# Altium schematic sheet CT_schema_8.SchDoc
size 252 x 159 mm
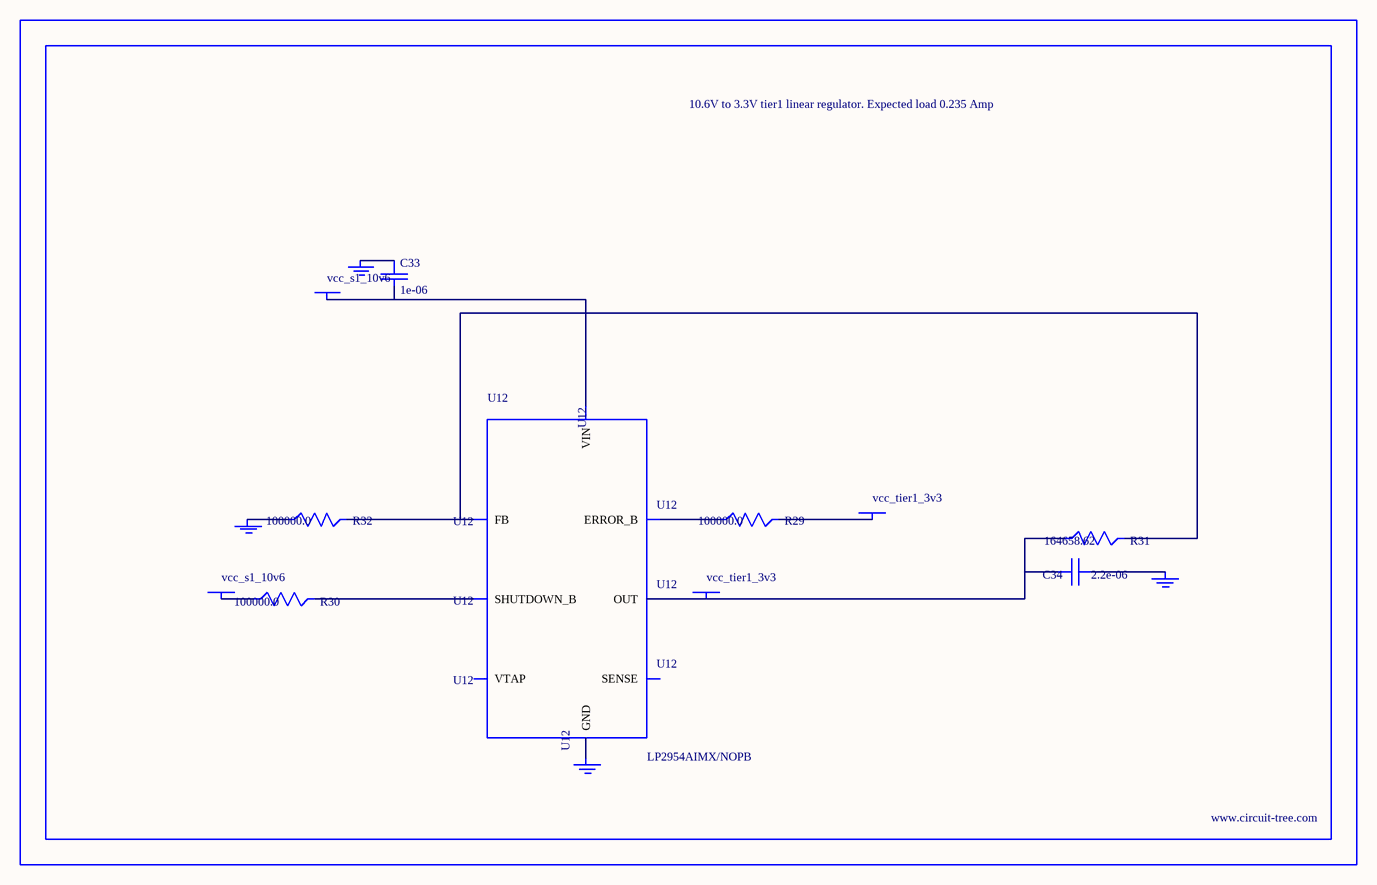
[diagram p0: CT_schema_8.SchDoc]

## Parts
BORDER7  (no value)
C33  1e-06  [EXV-9B]
C34  2.2e-06  [EXV-9B]
GND_INSTANCE_7_0  (no value)
GND_INSTANCE_7_1  (no value)
GND_INSTANCE_7_2  (no value)
GND_INSTANCE_7_3  (no value)
POWER_INSTANCE_7_0  vcc_s1_10v6
POWER_INSTANCE_7_1  vcc_tier1_3v3
POWER_INSTANCE_7_2  vcc_s1_10v6
POWER_INSTANCE_7_3  vcc_tier1_3v3
R29  100000.0  [R0603]
R30  100000.0  [R0603]
R31  164658.62  [R0603]
R32  100000.0  [R0603]
U12  LP2954AIMX/NOPB  [LP2954]

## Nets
NetC33_1: C33.1 GND_INSTANCE_7_2.0(GND)
NetC33_2: C33.2 POWER_INSTANCE_7_2.0(PWR) U12.8(VIN)
NetC34_1: C34.1 GND_INSTANCE_7_0.0(GND)
NetC34_2: C34.2 POWER_INSTANCE_7_3.0(PWR) R31.1 U12.1(OUT)
NetGND_INSTANCE_7_1_0: GND_INSTANCE_7_1.0(GND) R32.1
NetGND_INSTANCE_7_3_0: GND_INSTANCE_7_3.0(GND) U12.4(GND)
NetPOWER_INSTANCE_7_0_0: POWER_INSTANCE_7_0.0(PWR) R30.1
NetPOWER_INSTANCE_7_1_0: POWER_INSTANCE_7_1.0(PWR) R29.2
NetR29_1: R29.1 U12.5(ERROR_B)
NetR30_2: R30.2 U12.3(SHUTDOWN_B)
NetR31_2: R31.2 R32.2 U12.7(FB)

Not connected (* = marked no-connect by the designer): U12 2(SENSE) 6(VTAP)

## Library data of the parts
BORDER7 = BORDER_PAGE7
C33 = EDK105M050A9BAA
C34 = EDK225M050A9BAA
GND_INSTANCE_7_0-GND_INSTANCE_7_3 = GND
POWER_INSTANCE_7_0-POWER_INSTANCE_7_3 = PWR
R29 R30 R32 = RC0603JR-07100KL
R31 = R31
